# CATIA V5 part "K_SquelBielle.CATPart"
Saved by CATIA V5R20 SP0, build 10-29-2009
Part number: Squelette_bielle_motrice
Publications: "Plan_bielle_motrice", "Axe_pivot_bielle_1", "Axe_pivot_bielle_2", "Droite_bielle_motrice_1"
Bounding box of the stored display mesh (mm): x -178.986 to -89.007, y 0 to 40, z 48.706 to 50.68
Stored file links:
  G:\Khaled_CFAO_2011\ST2M\ST2M_GR2\jcoetard\Khaled\CAD_CATIA\K_SquelBielle.CATPart
  G:\Khaled_CFAO_2011\ST2M\ST2M_GR2\jcoetard\Khaled\CAD_CATIA\K_Squelette.CATProduct
  G:\Khaled_CFAO_2011\ST2M\ST2M_GR2\jcoetard\jcoetard\Maquette_jcoetard\Squelette General.CATPart
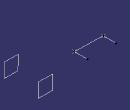
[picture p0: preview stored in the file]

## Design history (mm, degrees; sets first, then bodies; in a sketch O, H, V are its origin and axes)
Set1
  Plane1 "Plan_Ref": linked copy from another document
  Point1: linked copy from another document
  Point2: linked copy from another document
Set2 "Set géométrique"
  Plane2 "Plan_bielle_motrice": type Offset, RefPlane Plane1, Offset 107.303, reversed
  Line1 "Axe_pivot_bielle_1": type Normal, RefPoint Point1, RefSkin Plane2, Start 0, End 40
  Line2 "Axe_pivot_bielle_2": type Normal, RefPoint Point2, RefSkin Plane2, Start 0, End 40
  Line3 "Droite_bielle_motrice_1": type PtPt, FirstPoint Point1, SecondPoint Point2
Body1 (main body)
